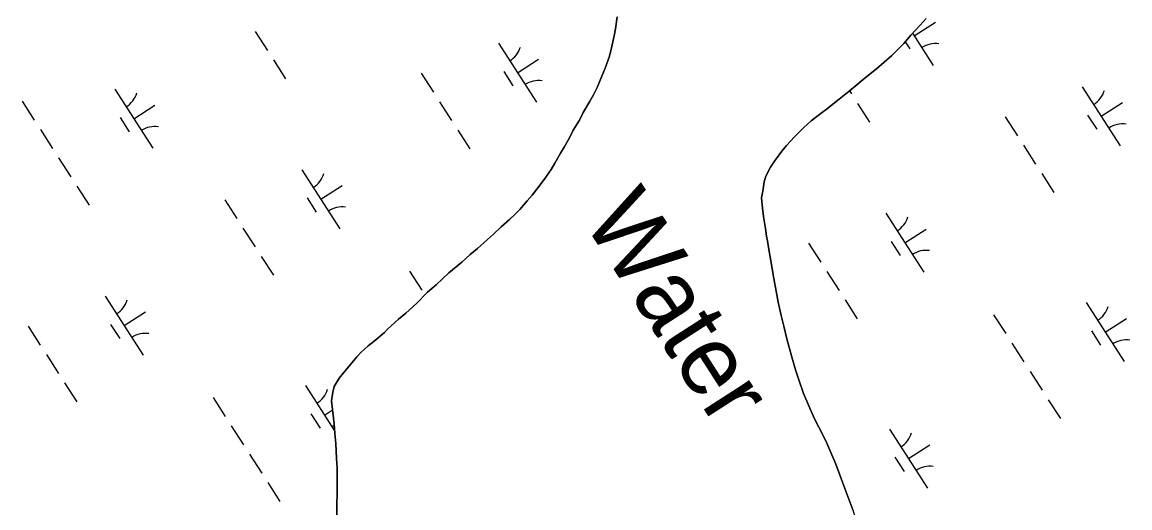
# Model space of a CAD drawing. Extents: x 3937982 to 3958556, y 219448 to 241894.
# Drawn here: x 3948523 to 3949312, y 225477 to 225823 of the extents above; entities that cross this region are included whole.
import ezdxf

# ---------------------------------------------------------------- set-up
doc = ezdxf.new("R2010")
doc.units = 0
for name, color, linetype in [('V-RIVR-IDEN', 7, 'Continuous'), ('V-TOPO-SHOR', 7, 'Continuous'), ('V-WETL-SWMP', 7, 'Continuous')]:
    doc.layers.add(name, color=color, linetype=linetype)

msp = doc.modelspace()

# ---------------------------------------------------------------- linework, layer by layer
at = {"layer": 'V-TOPO-SHOR'}
for points in [[(3948743.616, 225553.718), (3948744.409, 225559.798), (3948745.49, 225563.946), (3948749.045, 225569.766), (3948752.06, 225573.649), (3948756.996, 225579.478), (3948761.657, 225585.028), (3948764.401, 225588.081), (3948769.622, 225592.806), (3948774.019, 225596.146), (3948781.162, 225602.264), (3948783.358, 225604.76), (3948791.322, 225611.988), (3948796.545, 225616.159), (3948803.96, 225623.106), (3948811.921, 225631.161), (3948817.965, 225636.445), (3948827.029, 225644.782), (3948836.372, 225652.569), (3948842.139, 225657.849), (3948847.362, 225662.299), (3948854.503, 225668.691), (3948858.9, 225672.307), (3948864.393, 225677.585), (3948870.16, 225682.867), (3948874.004, 225686.48), (3948877.574, 225690.088), (3948882.784, 225696.195), (3948886.352, 225700.082), (3948889.639, 225704.518), (3948894.845, 225711.455), (3948899.774, 225718.385), (3948902.508, 225723.096), (3948906.61, 225730.024), (3948909.07, 225734.456), (3948912.896, 225741.108), (3948915.628, 225746.369), (3948920.002, 225753.574), (3948922.73, 225759.114), (3948927.107, 225766.595), (3948930.113, 225771.582), (3948932.569, 225776.843), (3948935.835, 225784.872), (3948938.287, 225790.686), (3948941.273, 225799.263), (3948942.897, 225805.071), (3948944.779, 225813.644), (3948945.578, 225818.619), (3948946.909, 225827.185)], [(3949166.778, 225825.991), (3949162.389, 225821.271), (3949155.805, 225814.054), (3949150.867, 225808.225), (3949142.358, 225799.613), (3949131.366, 225790.162), (3949123.397, 225783.764), (3949111.855, 225774.306), (3949104.709, 225768.465), (3949095.639, 225761.234), (3949092.888, 225759.284), (3949084.917, 225753.162), (3949079.697, 225748.438), (3949073.109, 225741.771), (3949067.346, 225735.662), (3949064.056, 225731.501), (3949058.852, 225724.29), (3949055.84, 225720.13), (3949052.563, 225713.761), (3949051.484, 225709.612), (3949050.417, 225702.978), (3949049.616, 225698.278), (3949050.212, 225690.825), (3949051.074, 225685.032), (3949052.506, 225676.479), (3949053.089, 225670.962), (3949053.937, 225667.652), (3949054.519, 225662.96), (3949056.231, 225653.306), (3949058.236, 225640.891), (3949059.948, 225631.79), (3949061.374, 225624.067), (3949063.639, 225614.415), (3949065.341, 225606.968), (3949067.604, 225597.869), (3949070.987, 225585.738), (3949073.807, 225575.814)], [(3949073.807, 225575.814), (3949075.777, 225569.473), (3949079.429, 225559.002), (3949082.509, 225551.842), (3949086.988, 225541.375), (3949090.338, 225535.042), (3949095.366, 225525.13), (3949098.168, 225518.519), (3949102.368, 225508.603), (3949104.889, 225502.266), (3949108.822, 225491.244), (3949113.028, 225479.947), (3949114.433, 225476.089), (3949117.812, 225464.788), (3949119.789, 225457.343), (3949122.613, 225446.866), (3949124.028, 225440.799), (3949125.175, 225433.904), (3949125.761, 225428.108), (3949124.411, 225422.576), (3949122.797, 225415.388), (3949120.35, 225409.023), (3949117.9, 225402.932), (3949099.192, 225381.559)], [(3948747.413, 225471.45), (3948747.37, 225478.628), (3948747.589, 225488.571), (3948747.546, 225495.751), (3948747.487, 225505.969), (3948747.171, 225512.594), (3948746.555, 225523.36), (3948745.961, 225530.537), (3948745.369, 225537.436), (3948744.206, 225547.646), (3948743.616, 225553.718)]]:
    msp.add_lwpolyline(points, dxfattribs=at)
at = {"layer": 'V-WETL-SWMP'}
for p, q in [((3948946.909, 225827.186), (3948945.578, 225818.618)), ((3949155.804, 225814.053), (3949162.389, 225821.271)), ((3949158.242, 225813.673), (3949173.378, 225823.416)), ((3949162.389, 225821.271), (3949166.779, 225825.991)), ((3948689.264, 225816.698), (3948697.924, 225803.244)), ((3948944.779, 225813.643), (3948942.896, 225805.071)), ((3948945.578, 225818.618), (3948944.779, 225813.643)), ((3949150.867, 225808.225), (3949155.804, 225814.053)), ((3949157.09, 225815.463), (3949171.773, 225792.652)), ((3948862.278, 225808.356), (3948889.34, 225766.312)), ((3948942.896, 225805.071), (3948941.273, 225799.263)), ((3949142.357, 225799.614), (3949150.867, 225808.225)), ((3949151.837, 225809.37), (3949155.002, 225804.452)), ((3948702.254, 225796.517), (3948710.913, 225783.063)), ((3948875.809, 225787.334), (3948890.945, 225797.077)), ((3948941.273, 225799.263), (3948938.286, 225790.685)), ((3949131.367, 225790.161), (3949142.357, 225799.614)), ((3948938.286, 225790.685), (3948935.835, 225784.871)), ((3949123.397, 225783.763), (3949131.367, 225790.161)), ((3948807.412, 225786.959), (3948816.072, 225773.505)), ((3948866.074, 225788.203), (3948872.569, 225778.113)), ((3948935.835, 225784.871), (3948932.569, 225776.844)), ((3949111.854, 225774.307), (3949123.397, 225783.763)), ((3948589.282, 225775.625), (3948616.344, 225733.582)), ((3948932.569, 225776.844), (3948930.114, 225771.583)), ((3949104.709, 225768.466), (3949111.854, 225774.307)), ((3949112.07, 225774.484), (3949113.486, 225772.285)), ((3949277.84, 225777.396), (3949304.903, 225735.353)), ((3948523.417, 225767.03), (3948532.076, 225753.576)), ((3948820.402, 225766.778), (3948829.062, 225753.324)), ((3948927.106, 225766.595), (3948922.731, 225759.113)), ((3948930.114, 225771.583), (3948927.106, 225766.595)), ((3949095.639, 225761.233), (3949104.709, 225768.466)), ((3949117.816, 225765.558), (3949126.476, 225752.104)), ((3949291.372, 225756.375), (3949306.507, 225766.117)), ((3948602.813, 225754.603), (3948617.948, 225764.346)), ((3948922.731, 225759.113), (3948920.003, 225753.575)), ((3949084.917, 225753.162), (3949092.889, 225759.284)), ((3949092.889, 225759.284), (3949095.639, 225761.233)), ((3949281.636, 225757.244), (3949288.131, 225747.154)), ((3948593.078, 225755.472), (3948599.572, 225745.382)), ((3948920.003, 225753.575), (3948915.627, 225746.369)), ((3949079.698, 225748.437), (3949084.917, 225753.162)), ((3949222.974, 225755.999), (3949231.634, 225742.546)), ((3948536.406, 225746.849), (3948545.066, 225733.395)), ((3948833.392, 225746.597), (3948842.052, 225733.143)), ((3948912.896, 225741.107), (3948909.069, 225734.457)), ((3948915.627, 225746.369), (3948912.896, 225741.107)), ((3949067.346, 225735.662), (3949073.109, 225741.771)), ((3949073.109, 225741.771), (3949079.698, 225748.437)), ((3948909.069, 225734.457), (3948906.61, 225730.024)), ((3949064.057, 225731.5), (3949067.346, 225735.662)), ((3949235.964, 225735.819), (3949244.624, 225722.365)), ((3948549.396, 225726.668), (3948558.056, 225713.215)), ((3948906.61, 225730.024), (3948902.508, 225723.096)), ((3949058.853, 225724.29), (3949064.057, 225731.5)), ((3948722.411, 225718.326), (3948749.473, 225676.283)), ((3948899.775, 225718.386), (3948894.845, 225711.454)), ((3948902.508, 225723.096), (3948899.775, 225718.386)), ((3949052.563, 225713.76), (3949055.839, 225720.13)), ((3949055.839, 225720.13), (3949058.853, 225724.29)), ((3948894.845, 225711.454), (3948889.639, 225704.519)), ((3949050.417, 225702.978), (3949051.483, 225709.611)), ((3949051.483, 225709.611), (3949052.563, 225713.76)), ((3949248.954, 225715.638), (3949257.614, 225702.184)), ((3948562.386, 225706.488), (3948571.046, 225693.034)), ((3948735.942, 225697.305), (3948751.077, 225707.047)), ((3948889.639, 225704.519), (3948886.351, 225700.082)), ((3949049.616, 225698.279), (3949050.417, 225702.978)), ((3948667.545, 225696.929), (3948676.205, 225683.475)), ((3948726.207, 225698.174), (3948732.702, 225688.083)), ((3948882.784, 225696.195), (3948877.573, 225690.089)), ((3948886.351, 225700.082), (3948882.784, 225696.195)), ((3949050.212, 225690.826), (3949049.616, 225698.279)), ((3948874.005, 225686.479), (3948870.16, 225682.866)), ((3948877.573, 225690.089), (3948874.005, 225686.479)), ((3949051.075, 225685.032), (3949050.212, 225690.826)), ((3949137.973, 225687.367), (3949165.035, 225645.324)), ((3948870.16, 225682.866), (3948864.392, 225677.586)), ((3949052.506, 225676.48), (3949051.075, 225685.032)), ((3948680.535, 225676.748), (3948689.195, 225663.295)), ((3948858.9, 225672.307), (3948854.503, 225668.691)), ((3948864.392, 225677.586), (3948858.9, 225672.307)), ((3949053.09, 225670.961), (3949052.506, 225676.48)), ((3949053.938, 225667.652), (3949053.09, 225670.961)), ((3949151.504, 225666.345), (3949166.64, 225676.088)), ((3948847.361, 225662.298), (3948842.14, 225657.849)), ((3948854.503, 225668.691), (3948847.361, 225662.298)), ((3949054.518, 225662.961), (3949053.938, 225667.652)), ((3949056.232, 225653.306), (3949054.518, 225662.961)), ((3949083.107, 225665.97), (3949091.767, 225652.516)), ((3949141.769, 225667.215), (3949148.264, 225657.124)), ((3948693.525, 225656.568), (3948702.184, 225643.114)), ((3948842.14, 225657.849), (3948836.372, 225652.568)), ((3948836.372, 225652.568), (3948827.029, 225644.782)), ((3949058.237, 225640.892), (3949056.232, 225653.306)), ((3948799.112, 225646.041), (3948807.772, 225632.587)), ((3948827.029, 225644.782), (3948817.965, 225636.444)), ((3949059.948, 225631.789), (3949058.237, 225640.892)), ((3949096.097, 225645.789), (3949104.757, 225632.335)), ((3948811.921, 225631.162), (3948803.96, 225623.107)), ((3948817.965, 225636.444), (3948811.921, 225631.162)), ((3949061.374, 225624.066), (3949059.948, 225631.789)), ((3948582.544, 225628.297), (3948609.606, 225586.253)), ((3948803.96, 225623.107), (3948796.545, 225616.16)), ((3949063.639, 225614.414), (3949061.374, 225624.066)), ((3949109.087, 225625.608), (3949117.747, 225612.155)), ((3949280.539, 225623.677), (3949307.601, 225581.634)), ((3948596.075, 225607.275), (3948611.21, 225617.018)), ((3948796.545, 225616.16), (3948791.323, 225611.987)), ((3949214.674, 225615.082), (3949223.334, 225601.628)), ((3948586.339, 225608.144), (3948592.834, 225598.054)), ((3948791.323, 225611.987), (3948783.358, 225604.761)), ((3949065.34, 225606.968), (3949063.639, 225614.414)), ((3949294.07, 225602.655), (3949309.206, 225612.398)), ((3948527.677, 225606.9), (3948536.337, 225593.446)), ((3948781.163, 225602.263), (3948774.019, 225596.146)), ((3948783.358, 225604.761), (3948781.163, 225602.263)), ((3949067.603, 225597.869), (3949065.34, 225606.968)), ((3949284.335, 225603.524), (3949290.83, 225593.434)), ((3948769.621, 225592.806), (3948764.402, 225588.081)), ((3948774.019, 225596.146), (3948769.621, 225592.806)), ((3949070.987, 225585.738), (3949067.603, 225597.869)), ((3949227.664, 225594.901), (3949236.324, 225581.447)), ((3948540.667, 225586.719), (3948549.327, 225573.265)), ((3948761.658, 225585.028), (3948756.996, 225579.477)), ((3948764.402, 225588.081), (3948761.658, 225585.028)), ((3949073.807, 225575.814), (3949070.987, 225585.738)), ((3948756.996, 225579.477), (3948752.06, 225573.65)), ((3949075.777, 225569.474), (3949073.807, 225575.814)), ((3948749.045, 225569.766), (3948745.49, 225563.946)), ((3948752.06, 225573.65), (3948749.045, 225569.766)), ((3949079.429, 225559.002), (3949075.777, 225569.474)), ((3949240.654, 225574.72), (3949249.314, 225561.267)), ((3948553.657, 225566.538), (3948562.317, 225553.084)), ((3948725.109, 225564.607), (3948745.796, 225532.468)), ((3948744.409, 225559.798), (3948743.617, 225553.718)), ((3948745.49, 225563.946), (3948744.409, 225559.798)), ((3948659.244, 225556.012), (3948667.904, 225542.558)), ((3948743.617, 225553.718), (3948744.205, 225547.646)), ((3949082.508, 225551.841), (3949079.429, 225559.002)), ((3949253.644, 225554.54), (3949262.304, 225541.086)), ((3948728.905, 225544.454), (3948735.4, 225534.364)), ((3948738.641, 225543.585), (3948744.256, 225547.199)), ((3948744.205, 225547.646), (3948745.369, 225537.436)), ((3949086.988, 225541.374), (3949082.508, 225551.841)), ((3948745.369, 225537.436), (3948745.962, 225530.536)), ((3949090.339, 225535.042), (3949086.988, 225541.374)), ((3948672.234, 225535.831), (3948680.894, 225522.377)), ((3948745.962, 225530.536), (3948746.556, 225523.36)), ((3949095.367, 225525.13), (3949090.339, 225535.042)), ((3949140.672, 225533.647), (3949167.734, 225491.604)), ((3948746.556, 225523.36), (3948747.172, 225512.594)), ((3949098.168, 225518.519), (3949095.367, 225525.13)), ((3949154.203, 225512.626), (3949169.338, 225522.368)), ((3948685.224, 225515.65), (3948693.884, 225502.196)), ((3948747.172, 225512.594), (3948747.487, 225505.968)), ((3949102.368, 225508.603), (3949098.168, 225518.519)), ((3949144.468, 225513.495), (3949150.963, 225503.404)), ((3948747.487, 225505.968), (3948747.547, 225495.751)), ((3949104.89, 225502.267), (3949102.368, 225508.603)), ((3949108.821, 225491.244), (3949104.89, 225502.267)), ((3948698.214, 225495.469), (3948706.874, 225482.016)), ((3948747.547, 225495.751), (3948747.589, 225488.572)), ((3949113.029, 225479.947), (3949108.821, 225491.244)), ((3948747.589, 225488.572), (3948747.371, 225478.629)), ((3948747.371, 225478.629), (3948747.413, 225471.45)), ((3949114.433, 225476.089), (3949113.029, 225479.947))]:
    msp.add_line(p, q, dxfattribs=at)
for centre, start, end in [((3948861.059, 225810.688), 301.99668, 343.540338), ((3949173.392, 225790.576), 81.996677, 123.540335), ((3948890.959, 225764.237), 81.996677, 123.540335), ((3948588.062, 225777.958), 301.99668, 343.540338), ((3949276.621, 225779.729), 301.99668, 343.540338), ((3948617.962, 225731.506), 81.996677, 123.540335), ((3949306.521, 225733.277), 81.996677, 123.540335), ((3948721.192, 225720.659), 301.99668, 343.540338), ((3948751.092, 225674.207), 81.996677, 123.540335), ((3949136.754, 225689.7), 301.99668, 343.540338), ((3949166.654, 225643.248), 81.996677, 123.540335), ((3948581.324, 225630.629), 301.99668, 343.540338), ((3949279.32, 225626.01), 301.99668, 343.540338), ((3948611.224, 225584.178), 81.996677, 123.540335), ((3949309.22, 225579.558), 81.996677, 123.540335), ((3948723.89, 225566.939), 301.99668, 343.540338), ((3948753.79, 225520.487), 118.099642, 123.540335), ((3949139.453, 225535.98), 301.99668, 343.540338), ((3949169.353, 225489.528), 81.996677, 123.540335)]:
    msp.add_arc(centre, 17.623, start, end, dxfattribs=at)

# ---------------------------------------------------------------- texts
at = {"layer": 'V-RIVR-IDEN'}
msp.add_text('Water', height=49.9999, rotation=302.768556, dxfattribs=at).set_placement((3948921.571, 225682.678))

doc.saveas('drawing.dxf')
